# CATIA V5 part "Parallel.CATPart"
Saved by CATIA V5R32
Part number: Part1
Bounding box of the stored display mesh (mm): x 0 to 150, y -29.343 to 29.343, z 0 to 29.343
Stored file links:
  D:\PROJECTS\Project 2022\CATIA V5 6R 2022\Resources\Part Files\c17_catia_v6_6r2022_prt\Parallel.CATPart
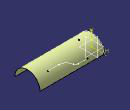
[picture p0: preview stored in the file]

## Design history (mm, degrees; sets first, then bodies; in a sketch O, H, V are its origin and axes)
Set1
  Sketch1 on yz-plane, origin (0, 0, 0), H (0, 1, 0), V (0, 0, 1)
    arc A1 centre (0, 0) radius 29.3431 from (29.3431, 0) to (-29.3431, 0) ccw
  Extrude1: Element1 Sketch1, Lim1 150, Lim2 0
  Sketch2 on zx-plane, origin (0, 0, 0), H (-1, 0, 0), V (0, 0, 1)
    line L1 (-121.5409, 21.8559) -> (-95.9964, 21.8559)
    line L2 (-59.5104, 9.3216) -> (-37.7891, 9.3216)
    arc A1 centre (-95.9964, -22.962) radius 44.8179 from (-95.9964, 21.8559) to (-68.4537, 12.394) cw
    arc A2 centre (-59.5104, 23.8743) radius 14.5527 from (-68.4537, 12.394) to (-59.5104, 9.3216) ccw
    radius A1 = 44.8179
    radius A2 = 14.5527
    horizontal: L1 H, L2 H
    tangency: A1 L1, A2 A1, A2 L2
  Extrude2: Element1 Sketch2, Lim1 150, Lim2 0
  Intersect1: ToIntersect1 Extrude2, ToIntersect2 Extrude1
Body1 (main body)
